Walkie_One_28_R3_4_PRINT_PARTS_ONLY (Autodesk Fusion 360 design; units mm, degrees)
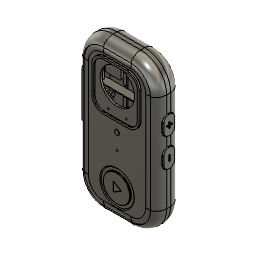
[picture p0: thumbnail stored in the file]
part number: 2026-09-14-15-06-09-075
part number: 2026-09-14-15-06-09-361
part number: 2026-09-14-15-06-09-395
part number: 2026-09-14-15-06-09-431
part number: 2026-09-14-15-06-09-435
part number: 2026-09-14-15-06-09-440
part number: 2026-09-14-15-06-09-447
part number: 2026-09-14-15-06-09-453
part number: 2026-09-14-15-06-09-457
part number: 2026-09-14-15-06-09-460
part number: 2026-09-14-15-06-09-463
part number: 2026-09-14-15-06-09-466
part number: 2026-09-14-15-06-09-468
part number: 2026-09-14-15-06-09-471
part number: 2026-09-14-15-06-09-474
part number: 2026-09-14-15-06-09-477
part number: 2026-09-14-15-06-09-481
part number: 2026-09-14-15-06-09-484
part number: 2026-09-14-15-06-09-487
part number: 2026-09-14-15-06-09-493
